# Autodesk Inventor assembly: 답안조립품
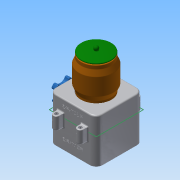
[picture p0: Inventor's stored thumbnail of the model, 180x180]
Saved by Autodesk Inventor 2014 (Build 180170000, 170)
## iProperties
Created: 2018-01
Part Number: 답안조립품
Document SubType Name: Assembly
Designer: net
Author: net
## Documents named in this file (9)
- C:\Users\net\Desktop\480107V1003\답안조립품.iam
- C:\Users\net\Desktop\480107V1003\본체.ipt
- C:\Users\net\Desktop\480107V1003\본체커버.ipt
- C:\Users\net\Desktop\480107V1003\핸들축.ipt
- C:\Users\net\Desktop\480107V1003\핸들.ipt
- C:\Users\net\Desktop\480107V1003\볼트 M3x12.ipt
- C:\Users\net\Desktop\480107V1003\볼트 M4x12.ipt
- C:\Users\net\Desktop\480107V1003\용기.ipt
- C:\Users\net\Desktop\480107V1003\용기캡.ipt
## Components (2 placed, 2 different names)
1. 핸들축:1
2. 핸들:1
